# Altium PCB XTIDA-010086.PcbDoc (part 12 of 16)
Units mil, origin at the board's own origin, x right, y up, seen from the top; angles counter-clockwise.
Board outline 14763.78 x 8267.72 mil, 6 copper layers (Top Layer, GND Layer, Signal Layer 1, Signal Layer 2, Power Layer, Bottom Layer), stack 62 mil thick; 1933 components, 1002 nets, 4886 pads, 6482 vias.
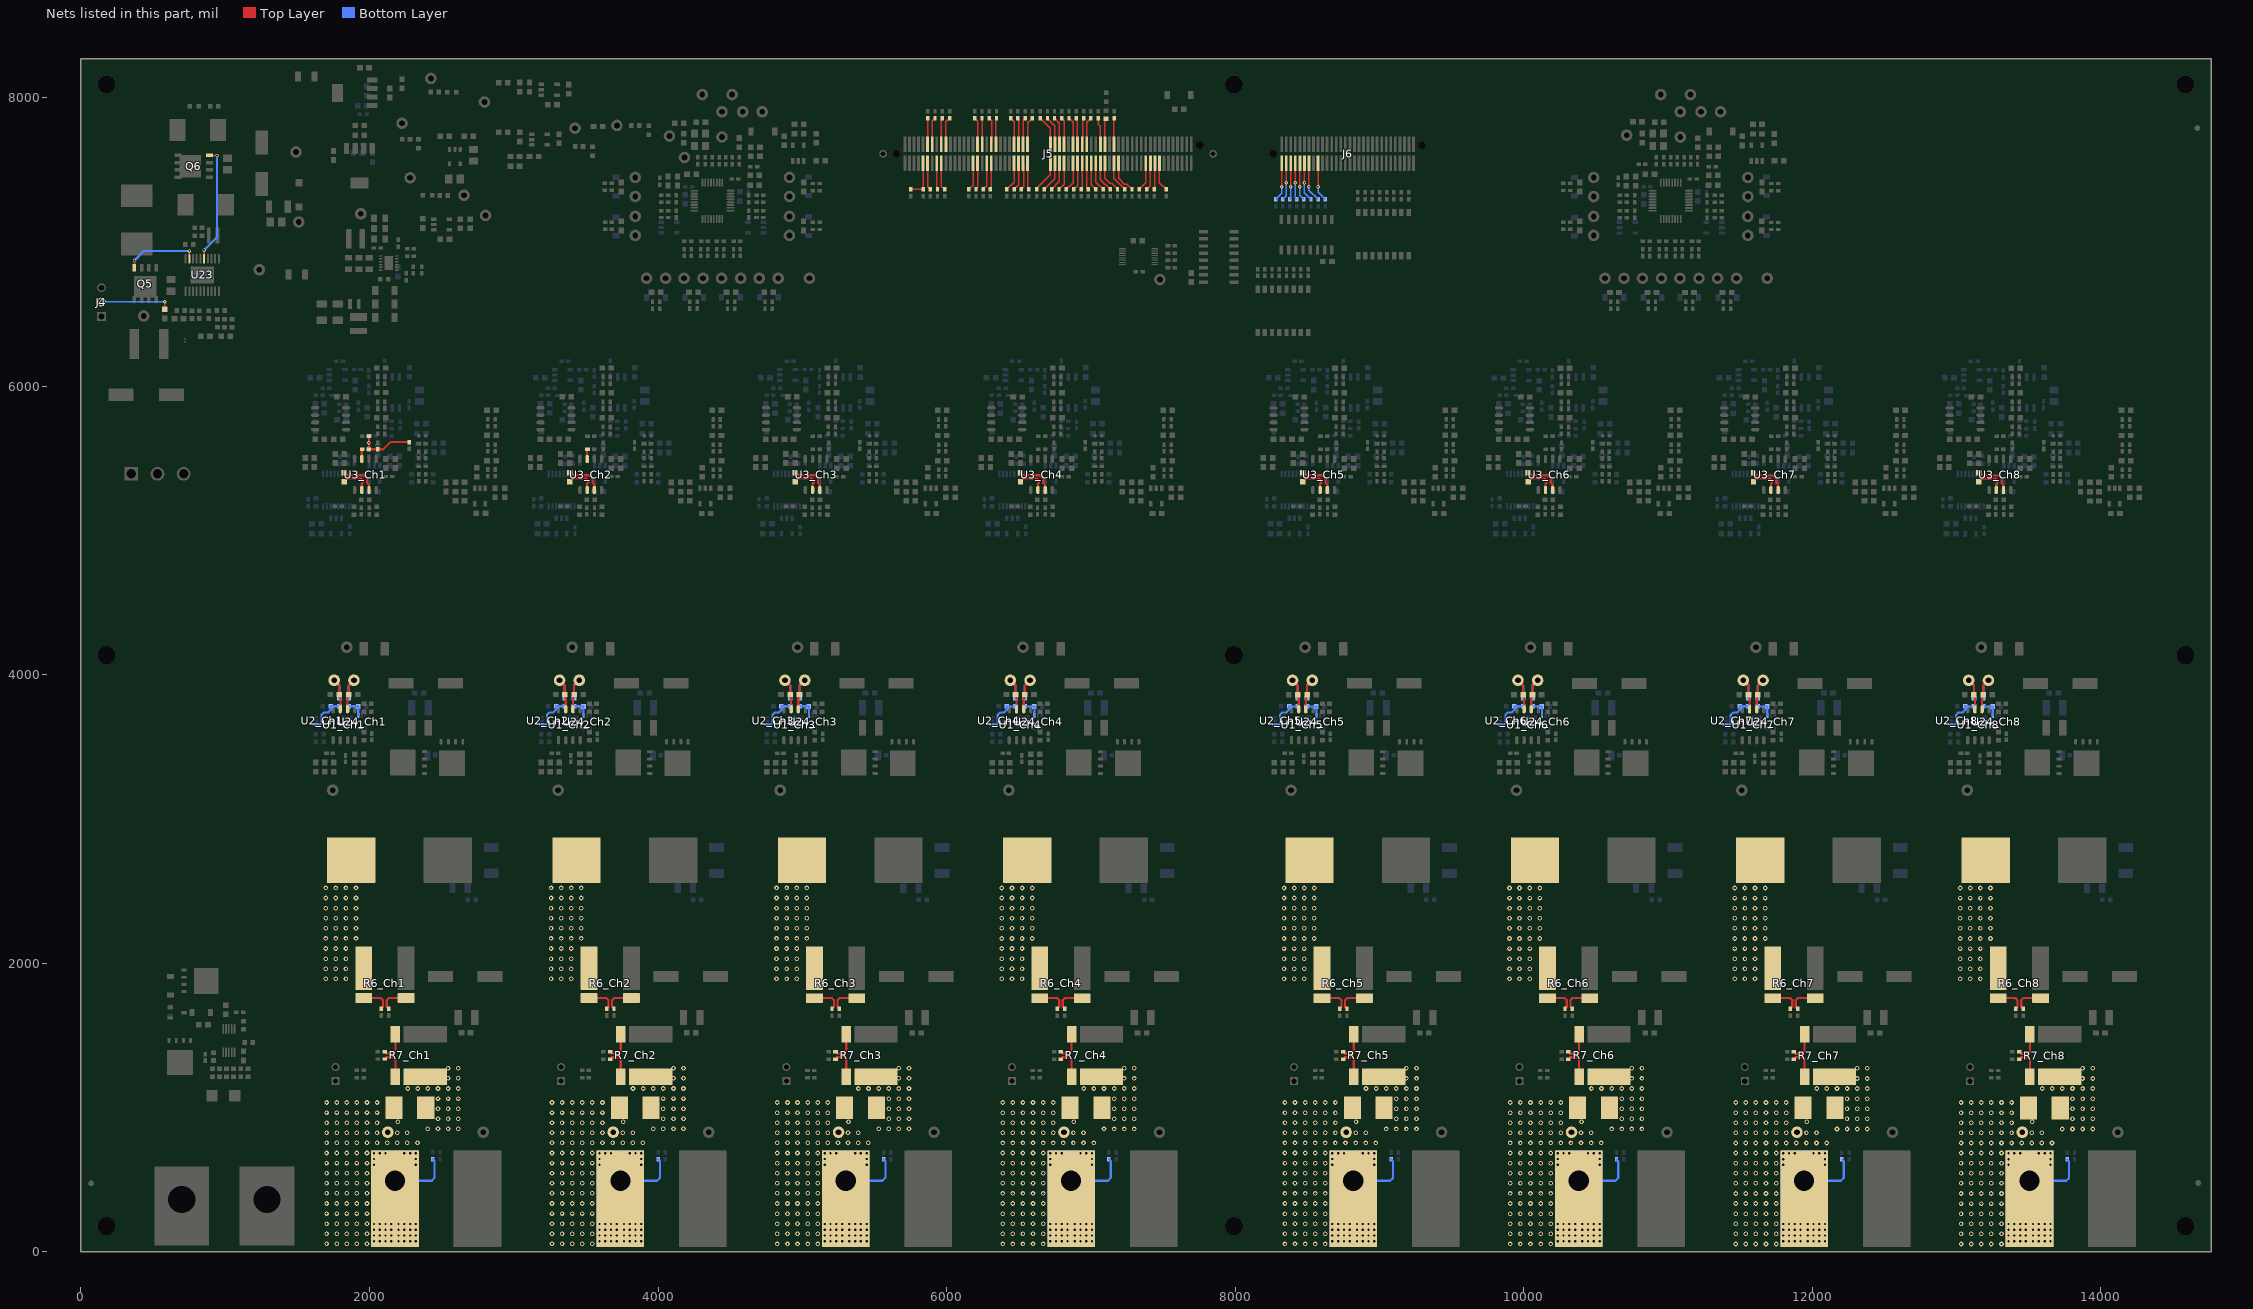
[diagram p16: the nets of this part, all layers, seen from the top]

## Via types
v1: diameter 32, hole 16, Top Layer to Bottom Layer, tented both sides, 4685 vias
v2: diameter 24, hole 12, Top Layer to Bottom Layer, tented both sides, 1013 vias
v3: diameter 32, hole 16, Top Layer to Bottom Layer, 728 vias
v4: diameter 19.68, hole 7.87, Top Layer to Bottom Layer, 40 vias
v5: diameter 214.57, hole 140, Top Layer to Bottom Layer, 16 vias

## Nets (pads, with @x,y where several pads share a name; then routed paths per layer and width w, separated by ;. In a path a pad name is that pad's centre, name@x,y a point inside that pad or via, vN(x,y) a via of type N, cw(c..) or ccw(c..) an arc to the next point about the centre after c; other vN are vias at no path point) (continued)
NetF1_Ch1_1: F1_Ch1.1 J1_Ch1.1 R10_Ch1.2 TP5_Ch1.1 | length 416.6
  Bottom Layer w15: v5(2177,493) 2432,493 2451.5,512.5 2451.5,628.88 R10_Ch1.2@2439,641.38
  other v1: 1703,55 1773,55 1843,55 1913,55 1983,55 1703,125 1773,125 1843,125 1913,125 1983,125 1703,195 1773,195 1843,195 1913,195 1983,195 1703,265 1773,265 1843,265 1913,265 1983,265 1703,335 1773,335 1843,335 1913,335 1983,335 1703,405 1773,405 1843,405 1913,405 1983,405 1703,475 1773,475 1843,475 1913,475 1983,475 1703,545 1773,545 1843,545 1913,545 1983,545 1703,615 1773,615 1843,615 1913,615 1983,615 1703,685 1773,685 1843,685 1913,685 1983,685 1703,755 1773,755 1843,755 1913,755 1983,755 2053,755 2123,755 2193,755 2263,755 2333,755 1703,825 1773,825 1843,825 1913,825 1983,825 2053,825 2193,825 2263,825 1703,895 1773,895 1843,895 1913,895 1983,895 2053,895 2196,902 1703,965 1773,965 1843,965 1913,965 1983,965 2053,965 1703,1035 1773,1035 1843,1035 1913,1035 1983,1035 2053,1035
  other v3: 2032,73 2072,73 2112,73 2152,73 2202,73 2242,73 2282,73 2322,73 2032,113 2072,113 2112,113 2152,113 2202,113 2242,113 2282,113 2322,113 2032,153 2072,153 2112,153 2152,153 2202,153 2242,153 2282,153 2322,153 2032,193 2072,193 2112,193 2152,193 2202,193 2242,193 2282,193 2322,193 2032,603 2322,603 2032,643 2322,643 2032,683 2072,683 2112,683 2242,683 2282,683 2322,683
NetF1_Ch1_2: F1_Ch1.2 R7_Ch1.1
  other v1: 2405,852 2475,852 2545,852 2615,852 2475,922 2545,922 2615,922 2475,992 2545,992 2615,992 2475,1062 2545,1062 2615,1062 2265,1132 2335,1132 2405,1132 2475,1132 2545,1132 2615,1132 2545,1202 2615,1202 2545,1272 2615,1272
NetF1_Ch2_1: F1_Ch2.1 J1_Ch2.1 R10_Ch2.2 TP5_Ch2.1 | length 416.6
  Bottom Layer w15: v5(3739,492.92) 3994,492.92 4013.5,512.42 4013.5,628.8 R10_Ch2.2@4001,641.3
  other v1: 3265,54.92 3335,54.92 3405,54.92 3475,54.92 3545,54.92 3265,124.92 3335,124.92 3405,124.92 3475,124.92 3545,124.92 3265,194.92 3335,194.92 3405,194.92 3475,194.92 3545,194.92 3265,264.92 3335,264.92 3405,264.92 3475,264.92 3545,264.92 3265,334.92 3335,334.92 3405,334.92 3475,334.92 3545,334.92 3265,404.92 3335,404.92 3405,404.92 3475,404.92 3545,404.92 3265,474.92 3335,474.92 3405,474.92 3475,474.92 3545,474.92 3265,544.92 3335,544.92 3405,544.92 3475,544.92 3545,544.92 3265,614.92 3335,614.92 3405,614.92 3475,614.92 3545,614.92 3265,684.92 3335,684.92 3405,684.92 3475,684.92 3545,684.92 3265,754.92 3335,754.92 3405,754.92 3475,754.92 3545,754.92 3615,754.92 3685,754.92 3755,754.92 3825,754.92 3895,754.92 3265,824.92 3335,824.92 3405,824.92 3475,824.92 3545,824.92 3615,824.92 3755,824.92 3825,824.92 3265,894.92 3335,894.92 3405,894.92 3475,894.92 3545,894.92 3615,894.92 3758,901.92 3265,964.92 3335,964.92 3405,964.92 3475,964.92 3545,964.92 3615,964.92 3265,1034.92 3335,1034.92 3405,1034.92 3475,1034.92 3545,1034.92 3615,1034.92
  other v3: 3594,72.92 3634,72.92 3674,72.92 3714,72.92 3764,72.92 3804,72.92 3844,72.92 3884,72.92 3594,112.92 3634,112.92 3674,112.92 3714,112.92 3764,112.92 3804,112.92 3844,112.92 3884,112.92 3594,152.92 3634,152.92 3674,152.92 3714,152.92 3764,152.92 3804,152.92 3844,152.92 3884,152.92 3594,192.92 3634,192.92 3674,192.92 3714,192.92 3764,192.92 3804,192.92 3844,192.92 3884,192.92 3594,602.92 3884,602.92 3594,642.92 3884,642.92 3594,682.92 3634,682.92 3674,682.92 3804,682.92 3844,682.92 3884,682.92
NetF1_Ch2_2: F1_Ch2.2 R7_Ch2.1
  other v1: 3967,851.92 4037,851.92 4107,851.92 4177,851.92 4037,921.92 4107,921.92 4177,921.92 4037,991.92 4107,991.92 4177,991.92 4037,1061.92 4107,1061.92 4177,1061.92 3827,1131.92 3897,1131.92 3967,1131.92 4037,1131.92 4107,1131.92 4177,1131.92 4107,1201.92 4177,1201.92 4107,1271.92 4177,1271.92
NetF1_Ch3_1: F1_Ch3.1 J1_Ch3.1 R10_Ch3.2 TP5_Ch3.1 | length 416.6
  Bottom Layer w15: v5(5301,492.84) 5556,492.84 5575.5,512.34 5575.5,628.72 R10_Ch3.2@5563,641.22
  other v1: 4827,54.84 4897,54.84 4967,54.84 5037,54.84 5107,54.84 4827,124.84 4897,124.84 4967,124.84 5037,124.84 5107,124.84 4827,194.84 4897,194.84 4967,194.84 5037,194.84 5107,194.84 4827,264.84 4897,264.84 4967,264.84 5037,264.84 5107,264.84 4827,334.84 4897,334.84 4967,334.84 5037,334.84 5107,334.84 4827,404.84 4897,404.84 4967,404.84 5037,404.84 5107,404.84 4827,474.84 4897,474.84 4967,474.84 5037,474.84 5107,474.84 4827,544.84 4897,544.84 4967,544.84 5037,544.84 5107,544.84 4827,614.84 4897,614.84 4967,614.84 5037,614.84 5107,614.84 4827,684.84 4897,684.84 4967,684.84 5037,684.84 5107,684.84 4827,754.84 4897,754.84 4967,754.84 5037,754.84 5107,754.84 5177,754.84 5247,754.84 5317,754.84 5387,754.84 5457,754.84 4827,824.84 4897,824.84 4967,824.84 5037,824.84 5107,824.84 5177,824.84 5317,824.84 5387,824.84 4827,894.84 4897,894.84 4967,894.84 5037,894.84 5107,894.84 5177,894.84 5320,901.84 4827,964.84 4897,964.84 4967,964.84 5037,964.84 5107,964.84 5177,964.84 4827,1034.84 4897,1034.84 4967,1034.84 5037,1034.84 5107,1034.84 5177,1034.84
  other v3: 5156,72.84 5196,72.84 5236,72.84 5276,72.84 5326,72.84 5366,72.84 5406,72.84 5446,72.84 5156,112.84 5196,112.84 5236,112.84 5276,112.84 5326,112.84 5366,112.84 5406,112.84 5446,112.84 5156,152.84 5196,152.84 5236,152.84 5276,152.84 5326,152.84 5366,152.84 5406,152.84 5446,152.84 5156,192.84 5196,192.84 5236,192.84 5276,192.84 5326,192.84 5366,192.84 5406,192.84 5446,192.84 5156,602.84 5446,602.84 5156,642.84 5446,642.84 5156,682.84 5196,682.84 5236,682.84 5366,682.84 5406,682.84 5446,682.84
NetF1_Ch3_2: F1_Ch3.2 R7_Ch3.1
  other v1: 5529,851.84 5599,851.84 5669,851.84 5739,851.84 5599,921.84 5669,921.84 5739,921.84 5599,991.84 5669,991.84 5739,991.84 5599,1061.84 5669,1061.84 5739,1061.84 5389,1131.84 5459,1131.84 5529,1131.84 5599,1131.84 5669,1131.84 5739,1131.84 5669,1201.84 5739,1201.84 5669,1271.84 5739,1271.84
NetF1_Ch4_1: F1_Ch4.1 J1_Ch4.1 R10_Ch4.2 TP5_Ch4.1 | length 416.6
  Bottom Layer w15: v5(6863,492.76) 7118,492.76 7137.5,512.26 7137.5,628.64 R10_Ch4.2@7125,641.14
  other v1: 6389,54.76 6459,54.76 6529,54.76 6599,54.76 6669,54.76 6389,124.76 6459,124.76 6529,124.76 6599,124.76 6669,124.76 6389,194.76 6459,194.76 6529,194.76 6599,194.76 6669,194.76 6389,264.76 6459,264.76 6529,264.76 6599,264.76 6669,264.76 6389,334.76 6459,334.76 6529,334.76 6599,334.76 6669,334.76 6389,404.76 6459,404.76 6529,404.76 6599,404.76 6669,404.76 6389,474.76 6459,474.76 6529,474.76 6599,474.76 6669,474.76 6389,544.76 6459,544.76 6529,544.76 6599,544.76 6669,544.76 6389,614.76 6459,614.76 6529,614.76 6599,614.76 6669,614.76 6389,684.76 6459,684.76 6529,684.76 6599,684.76 6669,684.76 6389,754.76 6459,754.76 6529,754.76 6599,754.76 6669,754.76 6739,754.76 6809,754.76 6879,754.76 6949,754.76 7019,754.76 6389,824.76 6459,824.76 6529,824.76 6599,824.76 6669,824.76 6739,824.76 6879,824.76 6949,824.76 6389,894.76 6459,894.76 6529,894.76 6599,894.76 6669,894.76 6739,894.76 6882,901.76 6389,964.76 6459,964.76 6529,964.76 6599,964.76 6669,964.76 6739,964.76 6389,1034.76 6459,1034.76 6529,1034.76 6599,1034.76 6669,1034.76 6739,1034.76
  other v3: 6718,72.76 6758,72.76 6798,72.76 6838,72.76 6888,72.76 6928,72.76 6968,72.76 7008,72.76 6718,112.76 6758,112.76 6798,112.76 6838,112.76 6888,112.76 6928,112.76 6968,112.76 7008,112.76 6718,152.76 6758,152.76 6798,152.76 6838,152.76 6888,152.76 6928,152.76 6968,152.76 7008,152.76 6718,192.76 6758,192.76 6798,192.76 6838,192.76 6888,192.76 6928,192.76 6968,192.76 7008,192.76 6718,602.76 7008,602.76 6718,642.76 7008,642.76 6718,682.76 6758,682.76 6798,682.76 6928,682.76 6968,682.76 7008,682.76
NetF1_Ch4_2: F1_Ch4.2 R7_Ch4.1
  other v1: 7091,851.76 7161,851.76 7231,851.76 7301,851.76 7161,921.76 7231,921.76 7301,921.76 7161,991.76 7231,991.76 7301,991.76 7161,1061.76 7231,1061.76 7301,1061.76 6951,1131.76 7021,1131.76 7091,1131.76 7161,1131.76 7231,1131.76 7301,1131.76 7231,1201.76 7301,1201.76 7231,1271.76 7301,1271.76
NetF1_Ch5_1: F1_Ch5.1 J1_Ch5.1 R10_Ch5.2 TP5_Ch5.1 | length 416.6
  Bottom Layer w15: v5(8818.7,492.69) 9073.7,492.69 9093.2,512.19 9093.2,628.56 R10_Ch5.2@9080.7,641.06
  other v1: 8344.7,54.69 8414.7,54.69 8484.7,54.69 8554.7,54.69 8624.7,54.69 8344.7,124.69 8414.7,124.69 8484.7,124.69 8554.7,124.69 8624.7,124.69 8344.7,194.69 8414.7,194.69 8484.7,194.69 8554.7,194.69 8624.7,194.69 8344.7,264.69 8414.7,264.69 8484.7,264.69 8554.7,264.69 8624.7,264.69 8344.7,334.69 8414.7,334.69 8484.7,334.69 8554.7,334.69 8624.7,334.69 8344.7,404.69 8414.7,404.69 8484.7,404.69 8554.7,404.69 8624.7,404.69 8344.7,474.69 8414.7,474.69 8484.7,474.69 8554.7,474.69 8624.7,474.69 8344.7,544.69 8414.7,544.69 8484.7,544.69 8554.7,544.69 8624.7,544.69 8344.7,614.69 8414.7,614.69 8484.7,614.69 8554.7,614.69 8624.7,614.69 8344.7,684.69 8414.7,684.69 8484.7,684.69 8554.7,684.69 8624.7,684.69 8344.7,754.69 8414.7,754.69 8484.7,754.69 8554.7,754.69 8624.7,754.69 8694.7,754.69 8764.7,754.69 8834.7,754.69 8904.7,754.69 8974.7,754.69 8344.7,824.69 8414.7,824.69 8484.7,824.69 8554.7,824.69 8624.7,824.69 8694.7,824.69 8834.7,824.69 8904.7,824.69 8344.7,894.69 8414.7,894.69 8484.7,894.69 8554.7,894.69 8624.7,894.69 8694.7,894.69 8837.7,901.69 8344.7,964.69 8414.7,964.69 8484.7,964.69 8554.7,964.69 8624.7,964.69 8694.7,964.69 8344.7,1034.69 8414.7,1034.69 8484.7,1034.69 8554.7,1034.69 8624.7,1034.69 8694.7,1034.69
  other v3: 8673.7,72.69 8713.7,72.69 8753.7,72.69 8793.7,72.69 8843.7,72.69 8883.7,72.69 8923.7,72.69 8963.7,72.69 8673.7,112.69 8713.7,112.69 8753.7,112.69 8793.7,112.69 8843.7,112.69 8883.7,112.69 8923.7,112.69 8963.7,112.69 8673.7,152.69 8713.7,152.69 8753.7,152.69 8793.7,152.69 8843.7,152.69 8883.7,152.69 8923.7,152.69 8963.7,152.69 8673.7,192.69 8713.7,192.69 8753.7,192.69 8793.7,192.69 8843.7,192.69 8883.7,192.69 8923.7,192.69 8963.7,192.69 8673.7,602.69 8963.7,602.69 8673.7,642.69 8963.7,642.69 8673.7,682.69 8713.7,682.69 8753.7,682.69 8883.7,682.69 8923.7,682.69 8963.7,682.69
NetF1_Ch5_2: F1_Ch5.2 R7_Ch5.1
  other v1: 9046.7,851.69 9116.7,851.69 9186.7,851.69 9256.7,851.69 9116.7,921.69 9186.7,921.69 9256.7,921.69 9116.7,991.69 9186.7,991.69 9256.7,991.69 9116.7,1061.69 9186.7,1061.69 9256.7,1061.69 8906.7,1131.69 8976.7,1131.69 9046.7,1131.69 9116.7,1131.69 9186.7,1131.69 9256.7,1131.69 9186.7,1201.69 9256.7,1201.69 9186.7,1271.69 9256.7,1271.69
NetF1_Ch6_1: F1_Ch6.1 J1_Ch6.1 R10_Ch6.2 TP5_Ch6.1 | length 416.6
  Bottom Layer w15: v5(10380.7,492.61) 10635.7,492.61 10655.2,512.11 10655.2,628.48 R10_Ch6.2@10642.7,640.98
  other v1: 9906.7,54.61 9976.7,54.61 10046.7,54.61 10116.7,54.61 10186.7,54.61 9906.7,124.61 9976.7,124.61 10046.7,124.61 10116.7,124.61 10186.7,124.61 9906.7,194.61 9976.7,194.61 10046.7,194.61 10116.7,194.61 10186.7,194.61 9906.7,264.61 9976.7,264.61 10046.7,264.61 10116.7,264.61 10186.7,264.61 9906.7,334.61 9976.7,334.61 10046.7,334.61 10116.7,334.61 10186.7,334.61 9906.7,404.61 9976.7,404.61 10046.7,404.61 10116.7,404.61 10186.7,404.61 9906.7,474.61 9976.7,474.61 10046.7,474.61 10116.7,474.61 10186.7,474.61 9906.7,544.61 9976.7,544.61 10046.7,544.61 10116.7,544.61 10186.7,544.61 9906.7,614.61 9976.7,614.61 10046.7,614.61 10116.7,614.61 10186.7,614.61 9906.7,684.61 9976.7,684.61 10046.7,684.61 10116.7,684.61 10186.7,684.61 9906.7,754.61 9976.7,754.61 10046.7,754.61 10116.7,754.61 10186.7,754.61 10256.7,754.61 10326.7,754.61 10396.7,754.61 10466.7,754.61 10536.7,754.61 9906.7,824.61 9976.7,824.61 10046.7,824.61 10116.7,824.61 10186.7,824.61 10256.7,824.61 10396.7,824.61 10466.7,824.61 9906.7,894.61 9976.7,894.61 10046.7,894.61 10116.7,894.61 10186.7,894.61 10256.7,894.61 10399.7,901.61 9906.7,964.61 9976.7,964.61 10046.7,964.61 10116.7,964.61 10186.7,964.61 10256.7,964.61 9906.7,1034.61 9976.7,1034.61 10046.7,1034.61 10116.7,1034.61 10186.7,1034.61 10256.7,1034.61
  other v3: 10235.7,72.61 10275.7,72.61 10315.7,72.61 10355.7,72.61 10405.7,72.61 10445.7,72.61 10485.7,72.61 10525.7,72.61 10235.7,112.61 10275.7,112.61 10315.7,112.61 10355.7,112.61 10405.7,112.61 10445.7,112.61 10485.7,112.61 10525.7,112.61 10235.7,152.61 10275.7,152.61 10315.7,152.61 10355.7,152.61 10405.7,152.61 10445.7,152.61 10485.7,152.61 10525.7,152.61 10235.7,192.61 10275.7,192.61 10315.7,192.61 10355.7,192.61 10405.7,192.61 10445.7,192.61 10485.7,192.61 10525.7,192.61 10235.7,602.61 10525.7,602.61 10235.7,642.61 10525.7,642.61 10235.7,682.61 10275.7,682.61 10315.7,682.61 10445.7,682.61 10485.7,682.61 10525.7,682.61
NetF1_Ch6_2: F1_Ch6.2 R7_Ch6.1
  other v1: 10608.7,851.61 10678.7,851.61 10748.7,851.61 10818.7,851.61 10678.7,921.61 10748.7,921.61 10818.7,921.61 10678.7,991.61 10748.7,991.61 10818.7,991.61 10678.7,1061.61 10748.7,1061.61 10818.7,1061.61 10468.7,1131.61 10538.7,1131.61 10608.7,1131.61 10678.7,1131.61 10748.7,1131.61 10818.7,1131.61 10748.7,1201.61 10818.7,1201.61 10748.7,1271.61 10818.7,1271.61
NetF1_Ch7_1: F1_Ch7.1 J1_Ch7.1 R10_Ch7.2 TP5_Ch7.1 | length 416.6
  Bottom Layer w15: v5(11942.7,492.53) 12197.7,492.53 12217.2,512.03 12217.2,628.41 R10_Ch7.2@12204.7,640.91
  other v1: 11468.7,54.53 11538.7,54.53 11608.7,54.53 11678.7,54.53 11748.7,54.53 11468.7,124.53 11538.7,124.53 11608.7,124.53 11678.7,124.53 11748.7,124.53 11468.7,194.53 11538.7,194.53 11608.7,194.53 11678.7,194.53 11748.7,194.53 11468.7,264.53 11538.7,264.53 11608.7,264.53 11678.7,264.53 11748.7,264.53 11468.7,334.53 11538.7,334.53 11608.7,334.53 11678.7,334.53 11748.7,334.53 11468.7,404.53 11538.7,404.53 11608.7,404.53 11678.7,404.53 11748.7,404.53 11468.7,474.53 11538.7,474.53 11608.7,474.53 11678.7,474.53 11748.7,474.53 11468.7,544.53 11538.7,544.53 11608.7,544.53 11678.7,544.53 11748.7,544.53 11468.7,614.53 11538.7,614.53 11608.7,614.53 11678.7,614.53 11748.7,614.53 11468.7,684.53 11538.7,684.53 11608.7,684.53 11678.7,684.53 11748.7,684.53 11468.7,754.53 11538.7,754.53 11608.7,754.53 11678.7,754.53 11748.7,754.53 11818.7,754.53 11888.7,754.53 11958.7,754.53 12028.7,754.53 12098.7,754.53 11468.7,824.53 11538.7,824.53 11608.7,824.53 11678.7,824.53 11748.7,824.53 11818.7,824.53 11958.7,824.53 12028.7,824.53 11468.7,894.53 11538.7,894.53 11608.7,894.53 11678.7,894.53 11748.7,894.53 11818.7,894.53 11961.7,901.53 11468.7,964.53 11538.7,964.53 11608.7,964.53 11678.7,964.53 11748.7,964.53 11818.7,964.53 11468.7,1034.53 11538.7,1034.53 11608.7,1034.53 11678.7,1034.53 11748.7,1034.53 11818.7,1034.53
  other v3: 11797.7,72.53 11837.7,72.53 11877.7,72.53 11917.7,72.53 11967.7,72.53 12007.7,72.53 12047.7,72.53 12087.7,72.53 11797.7,112.53 11837.7,112.53 11877.7,112.53 11917.7,112.53 11967.7,112.53 12007.7,112.53 12047.7,112.53 12087.7,112.53 11797.7,152.53 11837.7,152.53 11877.7,152.53 11917.7,152.53 11967.7,152.53 12007.7,152.53 12047.7,152.53 12087.7,152.53 11797.7,192.53 11837.7,192.53 11877.7,192.53 11917.7,192.53 11967.7,192.53 12007.7,192.53 12047.7,192.53 12087.7,192.53 11797.7,602.53 12087.7,602.53 11797.7,642.53 12087.7,642.53 11797.7,682.53 11837.7,682.53 11877.7,682.53 12007.7,682.53 12047.7,682.53 12087.7,682.53
NetF1_Ch7_2: F1_Ch7.2 R7_Ch7.1
  other v1: 12170.7,851.53 12240.7,851.53 12310.7,851.53 12380.7,851.53 12240.7,921.53 12310.7,921.53 12380.7,921.53 12240.7,991.53 12310.7,991.53 12380.7,991.53 12240.7,1061.53 12310.7,1061.53 12380.7,1061.53 12030.7,1131.53 12100.7,1131.53 12170.7,1131.53 12240.7,1131.53 12310.7,1131.53 12380.7,1131.53 12310.7,1201.53 12380.7,1201.53 12310.7,1271.53 12380.7,1271.53
NetF1_Ch8_1: F1_Ch8.1 J1_Ch8.1 R10_Ch8.2 TP5_Ch8.1 | length 416.6
  Bottom Layer w15: v5(13504.7,492.45) 13759.7,492.45 13779.2,511.95 13779.2,628.33 R10_Ch8.2@13766.7,640.83
  other v1: 13030.7,54.45 13100.7,54.45 13170.7,54.45 13240.7,54.45 13310.7,54.45 13030.7,124.45 13100.7,124.45 13170.7,124.45 13240.7,124.45 13310.7,124.45 13030.7,194.45 13100.7,194.45 13170.7,194.45 13240.7,194.45 13310.7,194.45 13030.7,264.45 13100.7,264.45 13170.7,264.45 13240.7,264.45 13310.7,264.45 13030.7,334.45 13100.7,334.45 13170.7,334.45 13240.7,334.45 13310.7,334.45 13030.7,404.45 13100.7,404.45 13170.7,404.45 13240.7,404.45 13310.7,404.45 13030.7,474.45 13100.7,474.45 13170.7,474.45 13240.7,474.45 13310.7,474.45 13030.7,544.45 13100.7,544.45 13170.7,544.45 13240.7,544.45 13310.7,544.45 13030.7,614.45 13100.7,614.45 13170.7,614.45 13240.7,614.45 13310.7,614.45 13030.7,684.45 13100.7,684.45 13170.7,684.45 13240.7,684.45 13310.7,684.45 13030.7,754.45 13100.7,754.45 13170.7,754.45 13240.7,754.45 13310.7,754.45 13380.7,754.45 13450.7,754.45 13520.7,754.45 13590.7,754.45 13660.7,754.45 13030.7,824.45 13100.7,824.45 13170.7,824.45 13240.7,824.45 13310.7,824.45 13380.7,824.45 13520.7,824.45 13590.7,824.45 13030.7,894.45 13100.7,894.45 13170.7,894.45 13240.7,894.45 13310.7,894.45 13380.7,894.45 13523.7,901.45 13030.7,964.45 13100.7,964.45 13170.7,964.45 13240.7,964.45 13310.7,964.45 13380.7,964.45 13030.7,1034.45 13100.7,1034.45 13170.7,1034.45 13240.7,1034.45 13310.7,1034.45 13380.7,1034.45
  other v3: 13359.7,72.45 13399.7,72.45 13439.7,72.45 13479.7,72.45 13529.7,72.45 13569.7,72.45 13609.7,72.45 13649.7,72.45 13359.7,112.45 13399.7,112.45 13439.7,112.45 13479.7,112.45 13529.7,112.45 13569.7,112.45 13609.7,112.45 13649.7,112.45 13359.7,152.45 13399.7,152.45 13439.7,152.45 13479.7,152.45 13529.7,152.45 13569.7,152.45 13609.7,152.45 13649.7,152.45 13359.7,192.45 13399.7,192.45 13439.7,192.45 13479.7,192.45 13529.7,192.45 13569.7,192.45 13609.7,192.45 13649.7,192.45 13359.7,602.45 13649.7,602.45 13359.7,642.45 13649.7,642.45 13359.7,682.45 13399.7,682.45 13439.7,682.45 13569.7,682.45 13609.7,682.45 13649.7,682.45
NetF1_Ch8_2: F1_Ch8.2 R7_Ch8.1
  other v1: 13732.7,851.45 13802.7,851.45 13872.7,851.45 13942.7,851.45 13802.7,921.45 13872.7,921.45 13942.7,921.45 13802.7,991.45 13872.7,991.45 13942.7,991.45 13802.7,1061.45 13872.7,1061.45 13942.7,1061.45 13592.7,1131.45 13662.7,1131.45 13732.7,1131.45 13802.7,1131.45 13872.7,1131.45 13942.7,1131.45 13872.7,1201.45 13942.7,1201.45 13872.7,1271.45 13942.7,1271.45
NetJ4_2: J4.2 R207.2 | length 491.4
  Top Layer w12: v2(581,6583.67) 581.5,6583.17 R207.2@581.5,6531.2
  Bottom Layer w12: J4.2@143,6582 144.67,6583.67 v2(581,6583.67)
NetJ5_9: J5.9 R221.2 R245.2 | length 265.2
  Top Layer w10: R221.2@5751.74,7362.97 R245.2@5837.25,7362.97 J5.9@5837.25,7542.7
NetJ5_11: J5.11 R246.2 | length 187.3
  Top Layer w10: J5.11@5868.74,7542.7 5868.74,7381.28 R246.2@5887.06,7362.97
NetJ5_12: J5.12 R247.2 | length 179.7
  Top Layer w10: J5.12@5868.74,7676.56 R247.2@5868.74,7856.29
NetJ5_14: J5.14 R248.2 | length 187.7
  Top Layer w10: J5.14@5900.24,7676.56 5900.24,7837.14 R248.2@5919.39,7856.29
NetJ5_15: J5.15 R249.2 | length 181.9
  Top Layer w10: J5.15@5931.73,7542.7 5931.73,7368.1 R249.2@5936.87,7362.97
NetJ5_17: J5.17 R250.2 | length 189.4
  Top Layer w10: J5.17@5963.23,7542.7 5963.23,7386.42 R250.2@5986.68,7362.97
NetJ5_18: J5.18 R251.2 | length 182.6
  Top Layer w10: J5.18@5963.23,7676.56 5963.23,7849.49 R251.2@5970.03,7856.29
NetJ5_20: J5.20 R252.2 | length 190.5
  Top Layer w10: J5.20@5994.73,7676.56 5994.73,7830.34 R252.2@6020.68,7856.29
NetJ5_31: J5.31 R253.2 | length 192.2
  Top Layer w10: R253.2@6153.68,7362.97 6183.7,7392.99 J5.31@6183.7,7542.7
NetJ5_33: J5.33 R254.2 | length 184.5
  Top Layer w10: R254.2@6203.68,7362.97 6215.2,7374.49 J5.33@6215.2,7542.7
NetJ5_34: J5.34 R255.2 | length 188.2
  Top Layer w10: R255.2@6194.68,7856.29 6215.2,7835.77 J5.34@6215.2,7676.56
NetJ5_36: J5.36 R256.2 | length 180.4
  Top Layer w10: R256.2@6245.01,7856.29 6246.7,7854.61 J5.36@6246.7,7676.56
NetJ5_37: J5.37 R257.2 | length 189.9
  Top Layer w10: R257.2@6253.68,7362.97 6278.19,7387.48 J5.37@6278.19,7542.7
NetJ5_39: J5.39 R258.2 | length 182.2
  Top Layer w10: R258.2@6303.68,7362.97 6309.69,7368.98 J5.39@6309.69,7542.7
NetJ5_40: J5.40 R259.2 | length 189.5
  Top Layer w10: R259.2@6295.35,7856.29 6314.28,7837.35 6314.28,7681.16 J5.40@6309.69,7676.56
NetJ5_42: J5.42 R260.2 | length 181.6
  Top Layer w10: J5.42@6341.18,7676.56 6341.18,7851.8 R260.2@6345.68,7856.29
NetJ5_49: J5.49 R261.2 | length 200.2
  Top Layer w10: R261.2@6417.68,7362.97 6467.17,7412.46 J5.49@6467.17,7542.7
NetJ5_50: J5.50 R262.2 | length 189.4
  Top Layer w10: R262.2@6443.89,7856.29 6467.17,7833.02 J5.50@6467.17,7676.56
NetJ5_51: J5.51 R263.2 | length 192.3
  Top Layer w10: R263.2@6468.01,7363.13 6498.66,7393.78 J5.51@6498.66,7542.7
NetJ5_52: J5.52 R264.2 | length 181.6
  Top Layer w10: R264.2@6494.15,7856.29 6498.66,7851.78 J5.52@6498.66,7676.56
NetJ5_53: J5.53 R265.2 | length 188.7
  Top Layer w10: R265.2@6518.35,7363.13 6535.28,7380.06 6535.28,7537.58 J5.53@6530.16,7542.7
NetJ5_54: J5.54 R266.2 | length 185.6
  Top Layer w10: J5.54@6530.16,7676.56 6530.16,7842.04 R266.2@6544.42,7856.29
NetJ5_55: J5.55 R267.2 | length 182.5
  Top Layer w10: J5.55@6561.66,7542.7 6561.66,7370.15 R267.2@6568.68,7363.13
NetJ5_56: J5.56 R268.2 | length 193.4
  Top Layer w10: J5.56@6561.66,7676.56 6561.66,7823.27 R268.2@6594.68,7856.29
NetJ5_57: J5.57 R269.2 | length 218.7
  Top Layer w10: R269.2@6624.68,7363.13 6624.68,7371.68 6719.14,7466.14 J5.57@6719.14,7542.7
NetJ5_58: J5.58 R293.1 | length 208.4
  Top Layer w10: R293.1@6650,7856.29 6719.14,7787.16 J5.58@6719.14,7676.56
NetJ5_59: J5.59 R271.2 | length 210.5
  Top Layer w10: R271.2@6676.01,7363.13 6750.63,7437.75 J5.59@6750.63,7542.7
NetJ5_60: J5.60 R294.1 | length 201.1
  Top Layer w10: R294.1@6699,7856.29 6750.63,7804.66 J5.60@6750.63,7676.56
NetJ5_61: J5.61 R273.2 | length 202.3
  Top Layer w10: R273.2@6727.35,7363.13 6782.13,7417.91 J5.61@6782.13,7542.7
NetJ5_62: J5.62 R295.1 | length 193.9
  Top Layer w10: R295.1@6748,7856.29 6782.13,7822.17 J5.62@6782.13,7676.56
NetJ5_63: J5.63 R275.2 | length 194
  Top Layer w10: R275.2@6778.68,7363.13 6813.62,7398.07 J5.63@6813.62,7542.7
NetJ5_64: J5.64 R274.2 | length 186.6
  Top Layer w10: R274.2@6797,7856.29 6813.62,7839.67 J5.64@6813.62,7676.56
NetJ5_67: J5.67 R277.2 | length 198.9
  Top Layer w10: R277.2@6830.01,7363.13 6876.62,7409.73 J5.67@6876.62,7542.7
NetJ5_68: J5.68 R278.2 | length 191.3
  Top Layer w10: R278.2@6848.28,7856.08 6876.62,7827.75 J5.68@6876.62,7676.56
NetJ5_69: J5.69 R279.2 | length 190.7
  Top Layer w10: R279.2@6881.35,7363.13 6908.11,7389.89 J5.69@6908.11,7542.7
NetJ5_70: J5.70 R280.2 | length 183.4
  Top Layer w10: R280.2@6898.78,7856.08 6905.28,7849.58 6905.28,7679.39 J5.70@6908.11,7676.56
NetJ5_71: J5.71 R281.2 | length 182.4
  Top Layer w10: R281.2@6932.68,7363.13 6939.61,7370.06 J5.71@6939.61,7542.7
NetJ5_72: J5.72 R282.2 | length 183.5
  Top Layer w10: J5.72@6939.61,7676.56 6942.28,7679.24 6942.28,7849.08 R282.2@6949.28,7856.08
NetJ5_73: J5.73 R276.1 | length 184.5
  Top Layer w10: J5.73@6971.1,7542.7 6971.1,7375.02 R276.1@6983,7363.13
NetJ5_74: J5.74 R283.2 | length 191.4
  Top Layer w10: J5.74@6971.1,7676.56 6971.1,7827.4 R283.2@6999.78,7856.08
NetJ5_75: J5.75 R284.2 | length 192.2
  Top Layer w10: J5.75@7002.6,7542.7 7002.6,7393.54 R284.2@7033.01,7363.13
NetJ5_77: J5.77 R286.2 | length 200.4
  Top Layer w10: J5.77@7034.1,7542.7 7034.1,7413.38 R286.2@7084.35,7363.13
NetJ5_79: J5.79 R288.2 | length 207
  Top Layer w10: J5.79@7065.59,7542.7 7065.59,7431.03 R288.2@7133,7363.62
NetJ5_80: J5.80 R289.2 | length 185.1
  Top Layer w10: R289.2@7052,7856.08 7052,7813 7065.59,7799.41 J5.80@7065.59,7676.56
NetJ5_81: J5.81 R285.1 | length 222.5
  Top Layer w10: J5.81@7097.09,7542.7 7097.09,7438.91 7131,7405 7143.27,7405 R285.1@7184.65,7363.62
NetJ5_82: J5.82 R59.1 | length 179.2
  Top Layer w10: J5.82@7097.09,7676.56 7097.09,7844.53 R59.1@7105,7852.44
NetJ5_85: J5.85 R272.1 | length 210.1
  Top Layer w10: J5.85@7160.08,7542.7 7160.08,7438.54 R272.1@7235,7363.62
NetJ5_86: J5.86 R58.2 | length 179.9
  Top Layer w10: J5.86@7160.08,7676.56 7160.08,7855.16 R58.2@7161,7856.08
NetJ5_87: J5.87 R270.1 | length 228.5
  Top Layer w10: J5.87@7191.58,7542.7 7191.58,7438.8 7231.56,7398.81 7249.81,7398.81 R270.1@7285,7363.62
NetJ5_99: J5.99 R292.2 | length 197.5
  Top Layer w10: R292.2@7336,7363.62 7380.55,7408.18 J5.99@7380.55,7542.7
NetJ5_101: J5.101 R297.2 | length 189
  Top Layer w10: R297.2@7388,7363.62 7412.05,7387.67 J5.101@7412.05,7542.7
NetJ5_103: J5.103 R298.2 | length 181
  Top Layer w10: R298.2@7439,7363.62 7443.55,7368.17 J5.103@7443.55,7542.7
NetJ5_105: J5.105 R296.2 | length 198.1
  Top Layer w10: J5.105@7475.04,7542.7 7475.04,7409.58 R296.2@7521,7363.62
NetJ6_121: J6.121 R164.2 | length 267.1
  Top Layer w10: v2(8322.28,7381) J6.121@8322.28,7542.7
  Bottom Layer w10: R164.2@8279.7,7293.24 8322.28,7335.83 v2(8322.28,7381)
NetJ6_123: J6.123 R165.2 | length 260
  Top Layer w10: J6.123@8353.78,7542.7 8354,7542.48 v2(8354,7409)
  Bottom Layer w10: R165.2@8328.8,7293.24 8354,7318.44 v2(8354,7409)
NetJ6_125: J6.125 R166.2 | length 252.5
  Top Layer w10: v2(8385.28,7381) J6.125@8385.28,7542.7
  Bottom Layer w10: R166.2@8377.9,7293.24 8385.28,7300.62 v2(8385.28,7381)
NetJ6_127: J6.127 R167.2 | length 253.7
  Top Layer w10: J6.127@8416.77,7542.7 8416.99,7542.48 v2(8416.99,7409)
  Bottom Layer w10: v2(8416.99,7409) 8416.99,7303.25 R167.2@8427,7293.24
NetJ6_129: J6.129 R168.2 | length 261
  Top Layer w10: v2(8448.27,7381) J6.129@8448.27,7542.7
  Bottom Layer w10: v2(8448.27,7381) 8448.27,7321.07 R168.2@8476.1,7293.24
NetJ6_131: J6.131 R169.2 | length 268.3
  Top Layer w10: J6.131@8479.77,7542.7 8479.99,7542.48 v2(8479.99,7409)
  Bottom Layer w10: v2(8479.99,7409) 8479.99,7338.46 R169.2@8525.2,7293.24
NetJ6_133: J6.133 R170.2 | length 275.6
  Top Layer w10: v2(8511.26,7381) J6.133@8511.26,7542.7
  Bottom Layer w10: v2(8511.26,7381) 8511.26,7356.28 R170.2@8574.3,7293.24
NetJ6_137: J6.137 R171.2 | length 269.8
  Top Layer w10: v2(8574.25,7381) J6.137@8574.25,7542.7
  Bottom Layer w10: v2(8574.25,7381) 8574.25,7342.39 R171.2@8623.4,7293.24
NetL2_Ch1_2: L2_Ch1.2 R6_Ch1.2
  other v1: 1697,1892 1767,1892 1837,1892 1697,1962 1767,1962 1837,1962 1697,2032 1767,2032 1837,2032 1697,2102 1767,2102 1837,2102 1697,2172 1767,2172 1837,2172 1907,2172 1697,2242 1767,2242 1837,2242 1907,2242 1697,2312 1767,2312 1837,2312 1907,2312 1697,2382 1767,2382 1837,2382 1907,2382 1697,2452 1767,2452 1837,2452 1907,2452 1697,2522 1767,2522 1837,2522 1907,2522
NetL2_Ch2_2: L2_Ch2.2 R6_Ch2.2
  other v1: 3259,1891.92 3329,1891.92 3399,1891.92 3259,1961.92 3329,1961.92 3399,1961.92 3259,2031.92 3329,2031.92 3399,2031.92 3259,2101.92 3329,2101.92 3399,2101.92 3259,2171.92 3329,2171.92 3399,2171.92 3469,2171.92 3259,2241.92 3329,2241.92 3399,2241.92 3469,2241.92 3259,2311.92 3329,2311.92 3399,2311.92 3469,2311.92 3259,2381.92 3329,2381.92 3399,2381.92 3469,2381.92 3259,2451.92 3329,2451.92 3399,2451.92 3469,2451.92 3259,2521.92 3329,2521.92 3399,2521.92 3469,2521.92
NetL2_Ch3_2: L2_Ch3.2 R6_Ch3.2
  other v1: 4821,1891.84 4891,1891.84 4961,1891.84 4821,1961.84 4891,1961.84 4961,1961.84 4821,2031.84 4891,2031.84 4961,2031.84 4821,2101.84 4891,2101.84 4961,2101.84 4821,2171.84 4891,2171.84 4961,2171.84 5031,2171.84 4821,2241.84 4891,2241.84 4961,2241.84 5031,2241.84 4821,2311.84 4891,2311.84 4961,2311.84 5031,2311.84 4821,2381.84 4891,2381.84 4961,2381.84 5031,2381.84 4821,2451.84 4891,2451.84 4961,2451.84 5031,2451.84 4821,2521.84 4891,2521.84 4961,2521.84 5031,2521.84
NetL2_Ch4_2: L2_Ch4.2 R6_Ch4.2
  other v1: 6383,1891.76 6453,1891.76 6523,1891.76 6383,1961.76 6453,1961.76 6523,1961.76 6383,2031.76 6453,2031.76 6523,2031.76 6383,2101.76 6453,2101.76 6523,2101.76 6383,2171.76 6453,2171.76 6523,2171.76 6593,2171.76 6383,2241.76 6453,2241.76 6523,2241.76 6593,2241.76 6383,2311.76 6453,2311.76 6523,2311.76 6593,2311.76 6383,2381.76 6453,2381.76 6523,2381.76 6593,2381.76 6383,2451.76 6453,2451.76 6523,2451.76 6593,2451.76 6383,2521.76 6453,2521.76 6523,2521.76 6593,2521.76
NetL2_Ch5_2: L2_Ch5.2 R6_Ch5.2
  other v1: 8338.7,1891.69 8408.7,1891.69 8478.7,1891.69 8338.7,1961.69 8408.7,1961.69 8478.7,1961.69 8338.7,2031.69 8408.7,2031.69 8478.7,2031.69 8338.7,2101.69 8408.7,2101.69 8478.7,2101.69 8338.7,2171.69 8408.7,2171.69 8478.7,2171.69 8548.7,2171.69 8338.7,2241.69 8408.7,2241.69 8478.7,2241.69 8548.7,2241.69 8338.7,2311.69 8408.7,2311.69 8478.7,2311.69 8548.7,2311.69 8338.7,2381.69 8408.7,2381.69 8478.7,2381.69 8548.7,2381.69 8338.7,2451.69 8408.7,2451.69 8478.7,2451.69 8548.7,2451.69 8338.7,2521.69 8408.7,2521.69 8478.7,2521.69 8548.7,2521.69
NetL2_Ch6_2: L2_Ch6.2 R6_Ch6.2
  other v1: 9900.7,1891.61 9970.7,1891.61 10040.7,1891.61 9900.7,1961.61 9970.7,1961.61 10040.7,1961.61 9900.7,2031.61 9970.7,2031.61 10040.7,2031.61 9900.7,2101.61 9970.7,2101.61 10040.7,2101.61 9900.7,2171.61 9970.7,2171.61 10040.7,2171.61 10110.7,2171.61 9900.7,2241.61 9970.7,2241.61 10040.7,2241.61 10110.7,2241.61 9900.7,2311.61 9970.7,2311.61 10040.7,2311.61 10110.7,2311.61 9900.7,2381.61 9970.7,2381.61 10040.7,2381.61 10110.7,2381.61 9900.7,2451.61 9970.7,2451.61 10040.7,2451.61 10110.7,2451.61 9900.7,2521.61 9970.7,2521.61 10040.7,2521.61 10110.7,2521.61
NetL2_Ch7_2: L2_Ch7.2 R6_Ch7.2
  other v1: 11462.7,1891.53 11532.7,1891.53 11602.7,1891.53 11462.7,1961.53 11532.7,1961.53 11602.7,1961.53 11462.7,2031.53 11532.7,2031.53 11602.7,2031.53 11462.7,2101.53 11532.7,2101.53 11602.7,2101.53 11462.7,2171.53 11532.7,2171.53 11602.7,2171.53 11672.7,2171.53 11462.7,2241.53 11532.7,2241.53 11602.7,2241.53 11672.7,2241.53 11462.7,2311.53 11532.7,2311.53 11602.7,2311.53 11672.7,2311.53 11462.7,2381.53 11532.7,2381.53 11602.7,2381.53 11672.7,2381.53 11462.7,2451.53 11532.7,2451.53 11602.7,2451.53 11672.7,2451.53 11462.7,2521.53 11532.7,2521.53 11602.7,2521.53 11672.7,2521.53
NetL2_Ch8_2: L2_Ch8.2 R6_Ch8.2
  other v1: 13024.7,1891.45 13094.7,1891.45 13164.7,1891.45 13024.7,1961.45 13094.7,1961.45 13164.7,1961.45 13024.7,2031.45 13094.7,2031.45 13164.7,2031.45 13024.7,2101.45 13094.7,2101.45 13164.7,2101.45 13024.7,2171.45 13094.7,2171.45 13164.7,2171.45 13234.7,2171.45 13024.7,2241.45 13094.7,2241.45 13164.7,2241.45 13234.7,2241.45 13024.7,2311.45 13094.7,2311.45 13164.7,2311.45 13234.7,2311.45 13024.7,2381.45 13094.7,2381.45 13164.7,2381.45 13234.7,2381.45 13024.7,2451.45 13094.7,2451.45 13164.7,2451.45 13234.7,2451.45 13024.7,2521.45 13094.7,2521.45 13164.7,2521.45 13234.7,2521.45
NetQ5_4: Q5.4 U23.19 | length 511.4
  Top Layer w12: U23.19@751.94,6881.91 v2(751.94,6935.7)
  Top Layer w15: Q5.4@371.5,6820.2 371.5,6870.2 v2(372,6870.7)
  Bottom Layer w15: v2(372,6870.7) 437,6935.7 v2(751.94,6935.7)
NetQ6_4: Q6.4 U23.15 | length 806.4
  Top Layer w12: U23.15@854.3,6881.91 v2(854.3,6942.7)
  Top Layer w15: Q6.4@891,7598.7 943.05,7598.7 v2(944,7597.75)
  Bottom Layer w15: v2(854.3,6942.7) 944,7032.4 v2(944,7597.75)
NetR1_Ch1_1: R1_Ch1.1 R2_Ch1.1 TP1_Ch1.1 U1_Ch1.2 | length 359.5
  Top Layer w15: U1_Ch1.2@1848.37,3760.35 1848.37,3854.07 R1_Ch1.1@1856.62,3862.31 1856.62,3925.31 TP1_Ch1.1@1892.42,3961.11
  Bottom Layer w15: R2_Ch1.1@1856.11,3835.67 1856.11,3924.81 TP1_Ch1.1@1892.42,3961.11
NetR1_Ch2_1: R1_Ch2.1 R2_Ch2.1 TP1_Ch2.1 U1_Ch2.2 | length 359.5
  Top Layer w15: U1_Ch2.2@3410.37,3760.27 3410.37,3853.99 R1_Ch2.1@3418.62,3862.24 3418.62,3925.23 TP1_Ch2.1@3454.42,3961.04
  Bottom Layer w15: R2_Ch2.1@3418.11,3835.59 3418.11,3924.73 TP1_Ch2.1@3454.42,3961.04
NetR1_Ch3_1: R1_Ch3.1 R2_Ch3.1 TP1_Ch3.1 U1_Ch3.2 | length 359.5
  Top Layer w15: U1_Ch3.2@4972.37,3760.19 4972.37,3853.91 R1_Ch3.1@4980.62,3862.16 4980.62,3925.15 TP1_Ch3.1@5016.42,3960.96
  Bottom Layer w15: R2_Ch3.1@4980.11,3835.52 4980.11,3924.65 TP1_Ch3.1@5016.42,3960.96
NetR1_Ch4_1: R1_Ch4.1 R2_Ch4.1 TP1_Ch4.1 U1_Ch4.2 | length 359.5
  Top Layer w15: U1_Ch4.2@6534.37,3760.12 6534.37,3853.83 R1_Ch4.1@6542.62,3862.08 6542.62,3925.08 TP1_Ch4.1@6578.42,3960.88
  Bottom Layer w15: R2_Ch4.1@6542.11,3835.44 6542.11,3924.57 TP1_Ch4.1@6578.42,3960.88
NetR1_Ch5_1: R1_Ch5.1 R2_Ch5.1 TP1_Ch5.1 U1_Ch5.2 | length 359.5
  Top Layer w15: U1_Ch5.2@8490.07,3760.04 8490.07,3853.75 R1_Ch5.1@8498.32,3862 8498.32,3925 TP1_Ch5.1@8534.12,3960.8
  Bottom Layer w15: R2_Ch5.1@8497.81,3835.36 8497.81,3924.49 TP1_Ch5.1@8534.12,3960.8
NetR1_Ch6_1: R1_Ch6.1 R2_Ch6.1 TP1_Ch6.1 U1_Ch6.2 | length 359.5
  Top Layer w15: U1_Ch6.2@10052.07,3759.96 10052.07,3853.67 R1_Ch6.1@10060.32,3861.92 10060.32,3924.92 TP1_Ch6.1@10096.12,3960.72
  Bottom Layer w15: R2_Ch6.1@10059.81,3835.28 10059.81,3924.41 TP1_Ch6.1@10096.12,3960.72
NetR1_Ch7_1: R1_Ch7.1 R2_Ch7.1 TP1_Ch7.1 U1_Ch7.2 | length 359.5
  Top Layer w15: U1_Ch7.2@11614.07,3759.88 11614.07,3853.6 R1_Ch7.1@11622.32,3861.84 11622.32,3924.84 TP1_Ch7.1@11658.12,3960.64
  Bottom Layer w15: R2_Ch7.1@11621.81,3835.2 11621.81,3924.34 TP1_Ch7.1@11658.12,3960.64
NetR1_Ch8_1: R1_Ch8.1 R2_Ch8.1 TP1_Ch8.1 U1_Ch8.2 | length 359.5
  Top Layer w15: U1_Ch8.2@13176.07,3759.8 13176.07,3853.52 R1_Ch8.1@13184.32,3861.76 13184.32,3924.76 TP1_Ch8.1@13220.12,3960.56
  Bottom Layer w15: R2_Ch8.1@13183.81,3835.12 13183.81,3924.26 TP1_Ch8.1@13220.12,3960.56
NetR2_Ch1_2: R2_Ch1.2 R216_Ch1.1 U24_Ch1.4 | length 127.7
  Bottom Layer w15: R2_Ch1.2@1856.11,3780.55 1920.05,3780.55 R216_Ch1.1@1921.49,3779.11 1922,3778.6 U24_Ch1.4@1922,3717.62
NetR2_Ch2_2: R2_Ch2.2 R216_Ch2.1 U24_Ch2.4 | length 127.7
  Bottom Layer w15: R2_Ch2.2@3418.11,3780.48 3482.05,3780.48 R216_Ch2.1@3483.49,3779.04 3484,3778.53 U24_Ch2.4@3484,3717.54
NetR2_Ch3_2: R2_Ch3.2 R216_Ch3.1 U24_Ch3.4 | length 127.7
  Bottom Layer w15: R2_Ch3.2@4980.11,3780.4 5044.05,3780.4 R216_Ch3.1@5045.49,3778.96 5046,3778.45 U24_Ch3.4@5046,3717.46
NetR2_Ch4_2: R2_Ch4.2 R216_Ch4.1 U24_Ch4.4 | length 127.7
  Bottom Layer w15: R2_Ch4.2@6542.11,3780.32 6606.05,3780.32 R216_Ch4.1@6607.49,3778.88 6608,3778.37 U24_Ch4.4@6608,3717.38
NetR2_Ch5_2: R2_Ch5.2 R216_Ch5.1 U24_Ch5.4 | length 127.7
  Bottom Layer w15: R2_Ch5.2@8497.81,3780.24 8561.75,3780.24 R216_Ch5.1@8563.19,3778.8 8563.7,3778.29 U24_Ch5.4@8563.7,3717.3
NetR2_Ch6_2: R2_Ch6.2 R216_Ch6.1 U24_Ch6.4 | length 127.7
  Bottom Layer w15: R2_Ch6.2@10059.81,3780.16 10123.75,3780.16 R216_Ch6.1@10125.19,3778.72 10125.7,3778.21 U24_Ch6.4@10125.7,3717.23
NetR2_Ch7_2: R2_Ch7.2 R216_Ch7.1 U24_Ch7.4 | length 127.7
  Bottom Layer w15: R2_Ch7.2@11621.81,3780.08 11685.75,3780.08 R216_Ch7.1@11687.19,3778.64 11687.7,3778.13 U24_Ch7.4@11687.7,3717.15
NetR2_Ch8_2: R2_Ch8.2 R216_Ch8.1 U24_Ch8.4 | length 127.7
  Bottom Layer w15: R2_Ch8.2@13183.81,3780 13247.75,3780 R216_Ch8.1@13249.19,3778.56 13249.7,3778.05 U24_Ch8.4@13249.7,3717.07
NetR3_Ch1_1: R3_Ch1.1 R5_Ch1.2 TP3_Ch1.1 U1_Ch1.3 | length 358.9
  Top Layer w15: TP3_Ch1.1@1755.81,3961.11 1791.61,3925.31 R5_Ch1.2@1791.61,3862.31 1798.37,3855.55 U1_Ch1.3@1798.37,3760.35
  Bottom Layer w15: TP3_Ch1.1@1755.81,3961.11 1792.11,3924.81 R3_Ch1.1@1792.11,3835.67
NetR3_Ch1_2: R3_Ch1.2 R217_Ch1.1 U2_Ch1.4 | length 264.1
  Bottom Layer w15: U2_Ch1.4@1629.71,3655.41 1661.41,3655.41 1669,3663 1669,3722 1685,3738 1713,3738 1731.39,3756.39 R217_Ch1.1@1731.39,3781.39 1732.23,3780.55 R3_Ch1.2@1792.11,3780.55
NetR3_Ch2_1: R3_Ch2.1 R5_Ch2.2 TP3_Ch2.1 U1_Ch2.3 | length 358.9
  Top Layer w15: TP3_Ch2.1@3317.81,3961.04 3353.61,3925.23 R5_Ch2.2@3353.61,3862.24 3360.37,3855.47 U1_Ch2.3@3360.37,3760.27
  Bottom Layer w15: TP3_Ch2.1@3317.81,3961.04 3354.11,3924.73 R3_Ch2.1@3354.11,3835.59
NetR3_Ch2_2: R3_Ch2.2 R217_Ch2.1 U2_Ch2.4 | length 264.1
  Bottom Layer w15: U2_Ch2.4@3191.71,3655.33 3223.41,3655.33 3231,3662.92 3231,3721.92 3247,3737.92 3275,3737.92 3293.39,3756.31 R217_Ch2.1@3293.39,3781.31 3294.23,3780.48 R3_Ch2.2@3354.11,3780.48
NetR3_Ch3_1: R3_Ch3.1 R5_Ch3.2 TP3_Ch3.1 U1_Ch3.3 | length 358.9
  Top Layer w15: TP3_Ch3.1@4879.81,3960.96 4915.61,3925.15 R5_Ch3.2@4915.61,3862.16 4922.37,3855.39 U1_Ch3.3@4922.37,3760.19
  Bottom Layer w15: TP3_Ch3.1@4879.81,3960.96 4916.11,3924.65 R3_Ch3.1@4916.11,3835.52
NetR3_Ch3_2: R3_Ch3.2 R217_Ch3.1 U2_Ch3.4 | length 264.1
  Bottom Layer w15: U2_Ch3.4@4753.71,3655.25 4785.41,3655.25 4793,3662.84 4793,3721.84 4809,3737.84 4837,3737.84 4855.39,3756.23 R217_Ch3.1@4855.39,3781.23 4856.23,3780.4 R3_Ch3.2@4916.11,3780.4
NetR3_Ch4_1: R3_Ch4.1 R5_Ch4.2 TP3_Ch4.1 U1_Ch4.3 | length 358.9
  Top Layer w15: TP3_Ch4.1@6441.81,3960.88 6477.61,3925.08 R5_Ch4.2@6477.61,3862.08 6484.37,3855.32 U1_Ch4.3@6484.37,3760.12
  Bottom Layer w15: TP3_Ch4.1@6441.81,3960.88 6478.11,3924.57 R3_Ch4.1@6478.11,3835.44
NetR3_Ch4_2: R3_Ch4.2 R217_Ch4.1 U2_Ch4.4 | length 265.3
  Bottom Layer w15: U2_Ch4.4@6315.71,3655.17 6347.41,3655.17 6355,3662.76 6355,3721.76 6371,3737.76 6399,3737.76 6417.39,3756.15 R217_Ch4.1@6417.39,3781.15 ; R3_Ch4.2@6478.11,3780.32 R217_Ch4.1@6418.23,3780.32 ; R217_Ch4.1@6417.39,3781.15 R217_Ch4.1@6418.23,3780.32 ; R217_Ch4.1@6417.39,3781.15 R217_Ch4.1@6418.23,3780.32
NetR3_Ch5_1: R3_Ch5.1 R5_Ch5.2 TP3_Ch5.1 U1_Ch5.3 | length 358.9
  Top Layer w15: TP3_Ch5.1@8397.51,3960.8 8433.31,3925 R5_Ch5.2@8433.31,3862 8440.07,3855.24 U1_Ch5.3@8440.07,3760.04
  Bottom Layer w15: TP3_Ch5.1@8397.51,3960.8 8433.81,3924.49 R3_Ch5.1@8433.81,3835.36
NetR3_Ch5_2: R3_Ch5.2 R217_Ch5.1 U2_Ch5.4 | length 264.1
  Bottom Layer w15: U2_Ch5.4@8271.41,3655.09 8303.11,3655.09 8310.7,3662.69 8310.7,3721.69 8326.7,3737.69 8354.7,3737.69 8373.09,3756.08 R217_Ch5.1@8373.09,3781.08 8373.93,3780.24 R3_Ch5.2@8433.81,3780.24
NetR3_Ch6_1: R3_Ch6.1 R5_Ch6.2 TP3_Ch6.1 U1_Ch6.3 | length 358.9
  Top Layer w15: TP3_Ch6.1@9959.51,3960.72 9995.31,3924.92 R5_Ch6.2@9995.31,3861.92 10002.07,3855.16 U1_Ch6.3@10002.07,3759.96
  Bottom Layer w15: TP3_Ch6.1@9959.51,3960.72 9995.81,3924.41 R3_Ch6.1@9995.81,3835.28
NetR3_Ch6_2: R3_Ch6.2 R217_Ch6.1 U2_Ch6.4 | length 265.3
  Bottom Layer w15: U2_Ch6.4@9833.41,3655.02 9865.11,3655.02 9872.7,3662.61 9872.7,3721.61 9888.7,3737.61 9916.7,3737.61 9935.09,3756 R217_Ch6.1@9935.09,3781 ; R217_Ch6.1@9935.93,3780.16 R217_Ch6.1@9935.09,3781 ; R3_Ch6.2@9995.81,3780.16 9994.98,3781 R217_Ch6.1@9935.09,3781
NetR3_Ch7_1: R3_Ch7.1 R5_Ch7.2 TP3_Ch7.1 U1_Ch7.3 | length 358.9
  Top Layer w15: TP3_Ch7.1@11521.51,3960.64 11557.31,3924.84 R5_Ch7.2@11557.31,3861.84 11564.07,3855.08 U1_Ch7.3@11564.07,3759.88
  Bottom Layer w15: TP3_Ch7.1@11521.51,3960.64 11557.81,3924.34 R3_Ch7.1@11557.81,3835.2
NetR3_Ch7_2: R3_Ch7.2 R217_Ch7.1 U2_Ch7.4 | length 265.3
  Bottom Layer w15: U2_Ch7.4@11395.41,3654.94 11427.11,3654.94 11434.7,3662.53 11434.7,3721.53 11450.7,3737.53 11478.7,3737.53 11497.09,3755.92 R217_Ch7.1@11497.09,3780.92 ; R217_Ch7.1@11497.93,3780.08 R217_Ch7.1@11497.09,3780.92 ; R3_Ch7.2@11557.81,3780.08 11556.98,3780.92 R217_Ch7.1@11497.09,3780.92
NetR3_Ch8_1: R3_Ch8.1 R5_Ch8.2 TP3_Ch8.1 U1_Ch8.3 | length 358.9
  Top Layer w15: TP3_Ch8.1@13083.51,3960.56 13119.31,3924.76 R5_Ch8.2@13119.31,3861.76 13126.07,3855 U1_Ch8.3@13126.07,3759.8
  Bottom Layer w15: TP3_Ch8.1@13083.51,3960.56 13119.81,3924.26 R3_Ch8.1@13119.81,3835.12
NetR3_Ch8_2: R3_Ch8.2 R217_Ch8.1 U2_Ch8.4 | length 265.3
  Bottom Layer w15: U2_Ch8.4@12957.41,3654.86 12989.11,3654.86 12996.7,3662.45 12996.7,3721.45 13012.7,3737.45 13040.7,3737.45 13059.09,3755.84 R217_Ch8.1@13059.09,3780.84 ; R3_Ch8.2@13119.81,3780 R217_Ch8.1@13059.93,3780 ; R217_Ch8.1@13059.09,3780.84 R217_Ch8.1@13059.93,3780 ; R217_Ch8.1@13059.09,3780.84 R217_Ch8.1@13059.93,3780
NetR6_Ch1_3: R6_Ch1.3 R13_Ch1.2 | length 205
  Top Layer w15: R13_Ch1.2@2132,1684.96 2119.5,1697.46 2119.5,1744 2134.49,1758.99 R6_Ch1.3@2254.05,1758.99
NetR6_Ch1_4: R6_Ch1.4 R12_Ch1.2 | length 205
  Top Layer w15: R6_Ch1.4@1959.95,1758.99 2079.51,1758.99 2094.5,1744 2094.5,1697.46 R12_Ch1.2@2082,1684.96
NetR6_Ch2_3: R6_Ch2.3 R13_Ch2.2 | length 205
  Top Layer w15: R13_Ch2.2@3694,1684.88 3681.5,1697.38 3681.5,1743.92 3696.49,1758.91 R6_Ch2.3@3816.05,1758.91
NetR6_Ch2_4: R6_Ch2.4 R12_Ch2.2 | length 205
  Top Layer w15: R6_Ch2.4@3521.95,1758.91 3641.51,1758.91 3656.5,1743.92 3656.5,1697.38 R12_Ch2.2@3644,1684.88
NetR6_Ch3_3: R6_Ch3.3 R13_Ch3.2 | length 205
  Top Layer w15: R13_Ch3.2@5256,1684.8 5243.5,1697.3 5243.5,1743.84 5258.49,1758.83 R6_Ch3.3@5378.05,1758.83
NetR6_Ch3_4: R6_Ch3.4 R12_Ch3.2 | length 205
  Top Layer w15: R6_Ch3.4@5083.95,1758.83 5203.51,1758.83 5218.5,1743.84 5218.5,1697.3 R12_Ch3.2@5206,1684.8
NetR6_Ch4_3: R6_Ch4.3 R13_Ch4.2 | length 205
  Top Layer w15: R13_Ch4.2@6818,1684.72 6805.5,1697.22 6805.5,1743.76 6820.49,1758.76 R6_Ch4.3@6940.05,1758.76
NetR6_Ch4_4: R6_Ch4.4 R12_Ch4.2 | length 205
  Top Layer w15: R6_Ch4.4@6645.95,1758.76 6765.51,1758.76 6780.5,1743.76 6780.5,1697.22 R12_Ch4.2@6768,1684.72
NetR6_Ch5_3: R6_Ch5.3 R13_Ch5.2 | length 205
  Top Layer w15: R13_Ch5.2@8773.7,1684.65 8761.2,1697.15 8761.2,1743.69 8776.19,1758.68 R6_Ch5.3@8895.75,1758.68
NetR6_Ch5_4: R6_Ch5.4 R12_Ch5.2 | length 205
  Top Layer w15: R6_Ch5.4@8601.65,1758.68 8721.21,1758.68 8736.2,1743.69 8736.2,1697.15 R12_Ch5.2@8723.7,1684.65
NetR6_Ch6_3: R6_Ch6.3 R13_Ch6.2 | length 205
  Top Layer w15: R13_Ch6.2@10335.7,1684.57 10323.2,1697.07 10323.2,1743.61 10338.19,1758.6 R6_Ch6.3@10457.75,1758.6
NetR6_Ch6_4: R6_Ch6.4 R12_Ch6.2 | length 205
  Top Layer w15: R6_Ch6.4@10163.65,1758.6 10283.21,1758.6 10298.2,1743.61 10298.2,1697.07 R12_Ch6.2@10285.7,1684.57
NetR6_Ch7_3: R6_Ch7.3 R13_Ch7.2 | length 205
  Top Layer w15: R13_Ch7.2@11897.7,1684.49 11885.2,1696.99 11885.2,1743.53 11900.19,1758.52 R6_Ch7.3@12019.75,1758.52
NetR6_Ch7_4: R6_Ch7.4 R12_Ch7.2 | length 205
  Top Layer w15: R6_Ch7.4@11725.65,1758.52 11845.21,1758.52 11860.2,1743.53 11860.2,1696.99 R12_Ch7.2@11847.7,1684.49
NetR6_Ch8_3: R6_Ch8.3 R13_Ch8.2 | length 205
  Top Layer w15: R13_Ch8.2@13459.7,1684.41 13447.2,1696.91 13447.2,1743.45 13462.19,1758.44 R6_Ch8.3@13581.75,1758.44
NetR6_Ch8_4: R6_Ch8.4 R12_Ch8.2 | length 205
  Top Layer w15: R6_Ch8.4@13287.65,1758.44 13407.21,1758.44 13422.2,1743.45 13422.2,1696.91 R12_Ch8.2@13409.7,1684.41
NetR7_Ch1_3: R7_Ch1.3 R16_Ch1.2 | length 205
  Top Layer w15: R16_Ch1.2@2105.96,1336 2118.46,1348.5 2165,1348.5 2179.99,1333.51 R7_Ch1.3@2179.99,1213.95
NetR7_Ch1_4: R7_Ch1.4 R15_Ch1.2 | length 205
  Top Layer w15: R15_Ch1.2@2105.96,1386 2118.46,1373.5 2165,1373.5 2179.99,1388.49 R7_Ch1.4@2179.99,1508.05
NetR7_Ch2_3: R7_Ch2.3 R16_Ch2.2 | length 205
  Top Layer w15: R16_Ch2.2@3667.96,1335.92 3680.46,1348.42 3727,1348.42 3741.99,1333.43 R7_Ch2.3@3741.99,1213.87
NetR7_Ch2_4: R7_Ch2.4 R15_Ch2.2 | length 205
  Top Layer w15: R15_Ch2.2@3667.96,1385.92 3680.46,1373.42 3727,1373.42 3741.99,1388.41 R7_Ch2.4@3741.99,1507.97
NetR7_Ch3_3: R7_Ch3.3 R16_Ch3.2 | length 205
  Top Layer w15: R16_Ch3.2@5229.96,1335.84 5242.46,1348.34 5289,1348.34 5303.99,1333.35 R7_Ch3.3@5303.99,1213.8
NetR7_Ch3_4: R7_Ch3.4 R15_Ch3.2 | length 205
  Top Layer w15: R15_Ch3.2@5229.96,1385.84 5242.46,1373.34 5289,1373.34 5303.99,1388.33 R7_Ch3.4@5303.99,1507.89
NetR7_Ch4_3: R7_Ch4.3 R16_Ch4.2 | length 205
  Top Layer w15: R16_Ch4.2@6791.96,1335.76 6804.46,1348.26 6851,1348.26 6865.99,1333.27 R7_Ch4.3@6865.99,1213.72
NetR7_Ch4_4: R7_Ch4.4 R15_Ch4.2 | length 205
  Top Layer w15: R15_Ch4.2@6791.96,1385.76 6804.46,1373.26 6851,1373.26 6865.99,1388.26 R7_Ch4.4@6865.99,1507.81
NetR7_Ch5_3: R7_Ch5.3 R16_Ch5.2 | length 205
  Top Layer w15: R16_Ch5.2@8747.66,1335.69 8760.16,1348.19 8806.7,1348.19 8821.69,1333.19 R7_Ch5.3@8821.69,1213.64
NetR7_Ch5_4: R7_Ch5.4 R15_Ch5.2 | length 205
  Top Layer w15: R15_Ch5.2@8747.66,1385.69 8760.16,1373.19 8806.7,1373.19 8821.69,1388.18 R7_Ch5.4@8821.69,1507.73
NetR7_Ch6_3: R7_Ch6.3 R16_Ch6.2 | length 205
  Top Layer w15: R16_Ch6.2@10309.66,1335.61 10322.16,1348.11 10368.7,1348.11 10383.69,1333.11 R7_Ch6.3@10383.69,1213.56
NetR7_Ch6_4: R7_Ch6.4 R15_Ch6.2 | length 205
  Top Layer w15: R15_Ch6.2@10309.66,1385.61 10322.16,1373.11 10368.7,1373.11 10383.69,1388.1 R7_Ch6.4@10383.69,1507.65
NetR7_Ch7_3: R7_Ch7.3 R16_Ch7.2 | length 205
  Top Layer w15: R16_Ch7.2@11871.66,1335.53 11884.16,1348.03 11930.7,1348.03 11945.69,1333.04 R7_Ch7.3@11945.69,1213.48
NetR7_Ch7_4: R7_Ch7.4 R15_Ch7.2 | length 205
  Top Layer w15: R15_Ch7.2@11871.66,1385.53 11884.16,1373.03 11930.7,1373.03 11945.69,1388.02 R7_Ch7.4@11945.69,1507.58
NetR7_Ch8_3: R7_Ch8.3 R16_Ch8.2 | length 205
  Top Layer w15: R16_Ch8.2@13433.66,1335.45 13446.16,1347.95 13492.7,1347.95 13507.69,1332.96 R7_Ch8.3@13507.69,1213.4
NetR7_Ch8_4: R7_Ch8.4 R15_Ch8.2 | length 205
  Top Layer w15: R15_Ch8.2@13433.66,1385.45 13446.16,1372.95 13492.7,1372.95 13507.69,1387.94 R7_Ch8.4@13507.69,1507.5
NetR30_Ch1_1: R30_Ch1.1 U3_Ch1.3 | length 257.4
  Top Layer w15: R30_Ch1.1@1826,5399.54 1828.82,5399.54 1846.66,5381.7 1957.79,5381.7 1983.79,5355.7 1983.79,5329.7 1997,5316.49 U3_Ch1.3@1997,5279.76
NetR30_Ch1_2: R30_Ch1.2 U3_Ch1.2 | length 213.1
  Top Layer w15: R30_Ch1.2@1826,5336.55 1848.15,5358.7 1942.79,5358.7 1954.79,5346.7 1954.79,5330.57 1947,5322.79 U3_Ch1.2@1947,5279.76
NetR30_Ch2_1: R30_Ch2.1 U3_Ch2.3 | length 257.4
  Top Layer w15: R30_Ch2.1@3388,5399.46 3390.82,5399.46 3408.66,5381.62 3519.79,5381.62 3545.79,5355.62 3545.79,5329.62 3559,5316.41 U3_Ch2.3@3559,5279.68
NetR30_Ch2_2: R30_Ch2.2 U3_Ch2.2 | length 213.1
  Top Layer w15: R30_Ch2.2@3388,5336.47 3410.15,5358.62 3504.79,5358.62 3516.79,5346.62 3516.79,5330.5 3509,5322.71 U3_Ch2.2@3509,5279.68
NetR30_Ch3_1: R30_Ch3.1 U3_Ch3.3 | length 257.4
  Top Layer w15: R30_Ch3.1@4950,5399.39 4952.82,5399.39 4970.66,5381.54 5081.79,5381.54 5107.79,5355.54 5107.79,5329.54 5121,5316.33 U3_Ch3.3@5121,5279.61
NetR30_Ch3_2: R30_Ch3.2 U3_Ch3.2 | length 213.1
  Top Layer w15: R30_Ch3.2@4950,5336.39 4972.15,5358.54 5066.79,5358.54 5078.79,5346.54 5078.79,5330.42 5071,5322.63 U3_Ch3.2@5071,5279.61
NetR30_Ch4_1: R30_Ch4.1 U3_Ch4.3 | length 257.4
  Top Layer w15: R30_Ch4.1@6512,5399.31 6514.82,5399.31 6532.66,5381.46 6643.79,5381.46 6669.79,5355.46 6669.79,5329.46 6683,5316.25 U3_Ch4.3@6683,5279.53
NetR30_Ch4_2: R30_Ch4.2 U3_Ch4.2 | length 213.1
  Top Layer w15: R30_Ch4.2@6512,5336.32 6534.15,5358.46 6628.79,5358.46 6640.79,5346.46 6640.79,5330.34 6633,5322.55 U3_Ch4.2@6633,5279.53
NetR30_Ch5_1: R30_Ch5.1 U3_Ch5.3 | length 257.4
  Top Layer w15: R30_Ch5.1@8467.7,5399.23 8470.52,5399.23 8488.36,5381.39 8599.49,5381.39 8625.49,5355.39 8625.49,5329.39 8638.7,5316.17 U3_Ch5.3@8638.7,5279.45
NetR30_Ch5_2: R30_Ch5.2 U3_Ch5.2 | length 213.1
  Top Layer w15: R30_Ch5.2@8467.7,5336.24 8489.85,5358.39 8584.49,5358.39 8596.49,5346.39 8596.49,5330.26 8588.7,5322.47 U3_Ch5.2@8588.7,5279.45
NetR30_Ch6_1: R30_Ch6.1 U3_Ch6.3 | length 257.4
  Top Layer w15: R30_Ch6.1@10029.7,5399.15 10032.52,5399.15 10050.36,5381.31 10161.49,5381.31 10187.49,5355.31 10187.49,5329.31 10200.7,5316.09 U3_Ch6.3@10200.7,5279.37
NetR30_Ch6_2: R30_Ch6.2 U3_Ch6.2 | length 213.1
  Top Layer w15: R30_Ch6.2@10029.7,5336.16 10051.85,5358.31 10146.49,5358.31 10158.49,5346.31 10158.49,5330.18 10150.7,5322.39 U3_Ch6.2@10150.7,5279.37
NetR30_Ch7_1: R30_Ch7.1 U3_Ch7.3 | length 257.4
  Top Layer w15: R30_Ch7.1@11591.7,5399.07 11594.52,5399.07 11612.36,5381.23 11723.49,5381.23 11749.49,5355.23 11749.49,5329.23 11762.7,5316.02 U3_Ch7.3@11762.7,5279.29
NetR30_Ch7_2: R30_Ch7.2 U3_Ch7.2 | length 213.1
  Top Layer w15: R30_Ch7.2@11591.7,5336.08 11613.85,5358.23 11708.49,5358.23 11720.49,5346.23 11720.49,5330.1 11712.7,5322.32 U3_Ch7.2@11712.7,5279.29
NetR30_Ch8_1: R30_Ch8.1 U3_Ch8.3 | length 257.4
  Top Layer w15: R30_Ch8.1@13153.7,5398.99 13156.52,5398.99 13174.36,5381.15 13285.49,5381.15 13311.49,5355.15 13311.49,5329.15 13324.7,5315.94 U3_Ch8.3@13324.7,5279.21
NetR30_Ch8_2: R30_Ch8.2 U3_Ch8.2 | length 213.1
  Top Layer w15: R30_Ch8.2@13153.7,5336 13175.85,5358.15 13270.49,5358.15 13282.49,5346.15 13282.49,5330.02 13274.7,5322.24 U3_Ch8.2@13274.7,5279.21
NetR31_Ch1_1: R31_Ch1.1 U3_Ch1.7 | length 68.7
  Top Layer w15: U3_Ch1.7@1947,5494.33 1947,5559.67 R31_Ch1.1@1949.38,5562.05
NetR31_Ch1_2: R31_Ch1.2 R32_Ch1.1 R41_Ch1.1 R43_Ch1.1 R48_Ch1.1 R175_Ch1.2 | length 484.6
  Top Layer w15: R175_Ch1.2@1996.62,5653.35 v2(1996.62,5607.7) R31_Ch1.2@1996.62,5562.05 2091.42,5562.05 ; 2091.45,5562.07 2095.45,5562.07 2145.04,5611.67 R41_Ch1.1@2275,5611.67
  Bottom Layer w15: R43_Ch1.1@1996.62,5562.05 v2(1996.62,5607.7) 1996.62,5655.29 R48_Ch1.1@1997.38,5656.05
NetR31_Ch2_1: R31_Ch2.1 U3_Ch2.7 | length 68.7
  Top Layer w15: U3_Ch2.7@3509,5494.25 3509,5559.59 R31_Ch2.1@3511.38,5561.97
